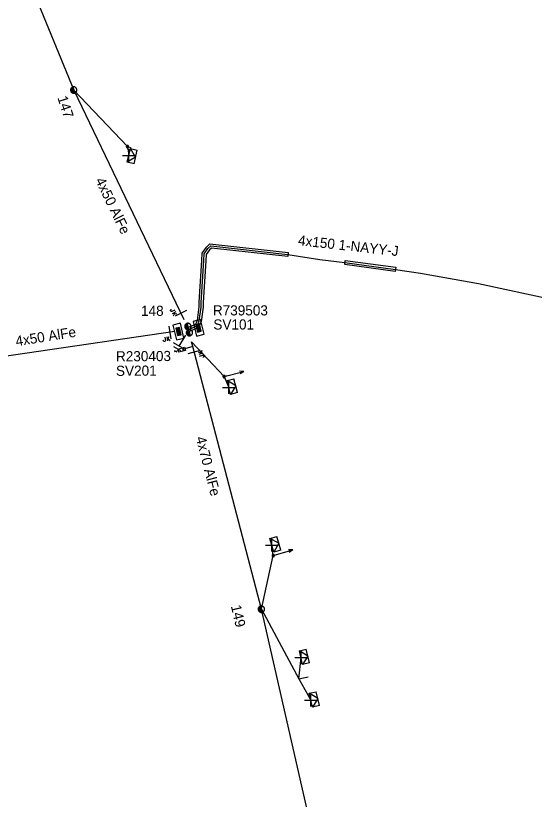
# Model space of a CAD drawing. Extents: x -544780 to -541582, y -1198995 to -1196551.
# Drawn here: x -542520.2 to -542469, y -1198913.7 to -1198836.4 of the extents above; entities that cross this region are included whole.
import ezdxf

# ---------------------------------------------------------------- set-up
doc = ezdxf.new("R2010")
doc.units = 0
for name, color, linetype in [('Vrstva 1', 7, 'Continuous'), ('Vrstva 13', 7, 'Continuous'), ('Vrstva 14', 7, 'Continuous'), ('Vrstva 15', 7, 'Continuous'), ('Vrstva 16', 7, 'Continuous'), ('Vrstva 18', 7, 'Continuous'), ('Vrstva 2', 7, 'Continuous'), ('Vrstva 20', 7, 'Continuous'), ('Vrstva 28', 7, 'Continuous'), ('Vrstva 29', 7, 'Continuous'), ('Vrstva 30', 7, 'Continuous'), ('Vrstva 31', 7, 'Continuous'), ('Vrstva 34', 7, 'Continuous'), ('Vrstva 5', 7, 'Continuous'), ('Vrstva 54', 7, 'Continuous'), ('Vrstva 59', 7, 'Continuous'), ('Vrstva 6', 7, 'Continuous'), ('Vrstva 8', 7, 'Continuous'), ('Vrstva 9', 7, 'Continuous')]:
    doc.layers.add(name, color=color, linetype=linetype)

# ---------------------------------------------------------------- blocks, each defined once
blk = doc.blocks.new('NN440')
at = {"layer": 'Vrstva 2'}
for points in [[(0.63, 0), (0.63, 0.06), (0.62, 0.13), (0.6, 0.19), (0.58, 0.25), (0.55, 0.31), (0.51, 0.37), (0.47, 0.42), (0.42, 0.46), (0.37, 0.51), (0.32, 0.54), (0.26, 0.57), (0.2, 0.59), (0.13, 0.61), (0.07, 0.62), (0, 0.63), (-0.06, 0.62), (-0.13, 0.61), (-0.19, 0.59), (-0.26, 0.57), (-0.31, 0.54), (-0.37, 0.51), (-0.42, 0.46), (-0.47, 0.42), (-0.51, 0.37), (-0.54, 0.31), (-0.57, 0.25), (-0.6, 0.19), (-0.62, 0.13), (-0.63, 0.06), (-0.63, 0), (-0.63, -0.07), (-0.62, -0.14), (-0.6, -0.2), (-0.57, -0.26), (-0.54, -0.32), (-0.51, -0.37), (-0.47, -0.43), (-0.42, -0.47), (-0.37, -0.51), (-0.31, -0.55), (-0.26, -0.58), (-0.19, -0.6), (-0.13, -0.62), (-0.06, -0.63), (0, -0.63), (0.07, -0.63), (0.13, -0.62), (0.2, -0.6), (0.26, -0.58), (0.32, -0.55), (0.37, -0.51), (0.42, -0.47), (0.47, -0.43), (0.51, -0.37), (0.55, -0.32), (0.58, -0.26), (0.6, -0.2), (0.62, -0.14), (0.63, -0.07), (0.63, 0)], [(-0.63, 0), (0.63, 0)], [(-0.6, -0.18), (0.57, -0.18)], [(-0.51, -0.32), (0.5, -0.32)], [(-0.37, -0.47), (0.35, -0.47)]]:
    blk.add_lwpolyline(points, dxfattribs=at)
blk = doc.blocks.new('NN450')
at = {"layer": 'Vrstva 2'}
for points in [[(0, 0), (0, 0.07), (-0.01, 0.13), (-0.03, 0.19), (-0.05, 0.25), (-0.08, 0.31), (-0.12, 0.37), (-0.16, 0.42), (-0.21, 0.46), (-0.26, 0.51), (-0.31, 0.54), (-0.37, 0.57), (-0.43, 0.59), (-0.5, 0.61), (-0.56, 0.62), (-0.63, 0.62), (-0.69, 0.62), (-0.75, 0.61), (-0.82, 0.59), (-0.88, 0.57), (-0.94, 0.54), (-0.99, 0.51), (-1.04, 0.46), (-1.09, 0.42), (-1.13, 0.37), (-1.17, 0.31), (-1.2, 0.25), (-1.22, 0.19), (-1.24, 0.13), (-1.25, 0.07), (-1.25, 0), (-1.25, -0.07), (-1.24, -0.13), (-1.22, -0.19), (-1.2, -0.25), (-1.17, -0.31), (-1.13, -0.37), (-1.09, -0.42), (-1.04, -0.46), (-0.99, -0.51), (-0.94, -0.54), (-0.88, -0.57), (-0.82, -0.59), (-0.75, -0.61), (-0.69, -0.62), (-0.62, -0.63), (-0.56, -0.62), (-0.5, -0.61), (-0.43, -0.59), (-0.37, -0.57), (-0.31, -0.54), (-0.26, -0.51), (-0.21, -0.46), (-0.16, -0.42), (-0.12, -0.37), (-0.08, -0.31), (-0.05, -0.25), (-0.03, -0.19), (-0.01, -0.13), (0, -0.07), (0, 0)], [(1.25, 0), (1.25, 0.07), (1.24, 0.13), (1.22, 0.19), (1.2, 0.25), (1.17, 0.31), (1.13, 0.37), (1.09, 0.42), (1.04, 0.46), (0.99, 0.51), (0.94, 0.54), (0.88, 0.57), (0.82, 0.59), (0.75, 0.61), (0.69, 0.62), (0.62, 0.62), (0.56, 0.62), (0.5, 0.61), (0.43, 0.59), (0.37, 0.57), (0.31, 0.54), (0.26, 0.51), (0.21, 0.46), (0.16, 0.42), (0.12, 0.37), (0.08, 0.31), (0.05, 0.25), (0.03, 0.19), (0.01, 0.13), (0, 0.07), (0, 0), (0, -0.07), (0.01, -0.13), (0.03, -0.19), (0.05, -0.25), (0.08, -0.31), (0.12, -0.37), (0.16, -0.42), (0.21, -0.46), (0.26, -0.51), (0.31, -0.54), (0.37, -0.57), (0.43, -0.59), (0.5, -0.61), (0.56, -0.62), (0.63, -0.63), (0.69, -0.62), (0.75, -0.61), (0.82, -0.59), (0.88, -0.57), (0.94, -0.54), (0.99, -0.51), (1.04, -0.46), (1.09, -0.42), (1.13, -0.37), (1.17, -0.31), (1.2, -0.25), (1.22, -0.19), (1.24, -0.13), (1.25, -0.07), (1.25, 0)], [(-1.25, 0), (1.25, 0)], [(-1.23, -0.16), (-0.02, -0.16)], [(-1.16, -0.32), (-0.09, -0.32)], [(-1.03, -0.47), (-0.22, -0.47)], [(0.02, -0.16), (1.23, -0.16)], [(0.09, -0.32), (1.16, -0.32)], [(0.22, -0.47), (1.03, -0.47)]]:
    blk.add_lwpolyline(points, dxfattribs=at)
blk = doc.blocks.new('NN560')
at = {"layer": 'Vrstva 2'}
for points in [[(1.999, -0.001), (1.59, 0.141)], [(0, -0.001), (1.999, -0.001)], [(1.999, -0.001), (1.59, -0.134)]]:
    blk.add_lwpolyline(points, dxfattribs=at)
blk = doc.blocks.new('NN840')
at = {"layer": 'Vrstva 15'}
for points in [[(0.003, 0.619), (0.003, -0.631)], [(-0.745, -0.71), (-0.745, -0.66)], [(-0.73, -0.764), (-0.745, -0.71)], [(-0.657, -0.798), (-0.73, -0.764)], [(-0.558, -0.764), (-0.627, -0.798)], [(-0.538, -0.71), (-0.558, -0.764)], [(-0.538, -0.385), (-0.538, -0.71)], [(-0.332, -0.385), (-0.332, -0.798)], [(-0.332, -0.641), (-0.125, -0.385)], [(-0.263, -0.557), (-0.091, -0.798)], [(-0.627, -0.798), (-0.657, -0.798)]]:
    blk.add_lwpolyline(points, dxfattribs=at)
blk = doc.blocks.new('NN800')
at = {"layer": 'Vrstva 1'}
for points in [[(-0.442, 0.442), (0.442, -0.442)], [(-0.442, -0.442), (0.442, 0.442)]]:
    blk.add_lwpolyline(points, dxfattribs=at)
blk = doc.blocks.new('NN820')
at = {"layer": 'Vrstva 13'}
for points in [[(-0.003, 0.004), (-0.003, -1.049)], [(-0.165, -0.813), (0.165, -0.813)], [(-0.165, -1.473), (-0.165, -0.813)], [(0.165, -1.473), (-0.165, -1.473)], [(-0.003, -1.049), (-0.062, -0.926)], [(-0.003, -1.049), (0.057, -0.926)], [(-0.003, -1.473), (-0.003, -1.871)], [(0.165, -0.813), (0.165, -1.473)]]:
    blk.add_lwpolyline(points, dxfattribs=at)
blk = doc.blocks.new('NN620')
at = {"layer": 'Vrstva 8'}
for points in [[(0.752, 0.004), (-0.748, 0.004)], [(-0.748, 0.004), (-0.748, -0.746)], [(0.752, -0.746), (0.752, 0.004)], [(-0.748, -0.746), (0.752, -0.746)], [(0.368, -0.18), (-0.376, -0.18)], [(-0.376, -0.18), (-0.376, -0.558)], [(-0.376, -0.558), (0.368, -0.558)], [(0.321, -0.227), (-0.329, -0.227)], [(-0.329, -0.227), (-0.329, -0.51)], [(-0.329, -0.51), (0.321, -0.51)], [(0.274, -0.274), (-0.281, -0.274)], [(-0.281, -0.274), (-0.281, -0.463)], [(-0.281, -0.463), (0.274, -0.463)], [(0.227, -0.321), (-0.234, -0.321)], [(-0.234, -0.321), (-0.234, -0.416)], [(-0.234, -0.416), (0.227, -0.416)], [(-0.193, -0.369), (0.185, -0.369)], [(0.227, -0.416), (0.227, -0.321)], [(0.274, -0.463), (0.274, -0.274)], [(0.321, -0.51), (0.321, -0.227)], [(0.368, -0.558), (0.368, -0.18)]]:
    blk.add_lwpolyline(points, dxfattribs=at)
blk = doc.blocks.new('NN630')
at = {"layer": 'Vrstva 9'}
for points in [[(-0.003, -0.7), (-0.703, 0)], [(-0.703, -0.7), (-0.703, 0), (0.697, 0), (0.697, -0.7)], [(-0.703, -0.7), (0.697, -0.7)], [(-0.003, -0.7), (0.697, 0)]]:
    blk.add_lwpolyline(points, dxfattribs=at)
blk = doc.blocks.new('NN810')
at = {"layer": 'Vrstva 14'}
for points in [[(0.004, -0.64), (0.004, -1.89)], [(0.629, -1.89), (-0.621, -1.89)], [(0.388, -2.2), (-0.399, -2.2)], [(0.004, -2.515), (-0.124, -2.515)], [(0.137, -2.515), (0.004, -2.515)]]:
    blk.add_lwpolyline(points, dxfattribs=at)
blk = doc.blocks.new('NN500')
at = {"layer": 'Vrstva 2'}
for points in [[(0, -0.24), (0.02, -0.23), (0.05, -0.23), (0.07, -0.22), (0.09, -0.22), (0.12, -0.2), (0.14, -0.19), (0.16, -0.18), (0.17, -0.16), (0.19, -0.14), (0.2, -0.12), (0.21, -0.1), (0.22, -0.07), (0.23, -0.05), (0.23, -0.02), (0.23, 0), (0.23, 0.02), (0.23, 0.05), (0.22, 0.07), (0.21, 0.1), (0.2, 0.12), (0.19, 0.14), (0.17, 0.16), (0.16, 0.17), (0.14, 0.19), (0.12, 0.2), (0.09, 0.21), (0.07, 0.22), (0.05, 0.23), (0.02, 0.23), (0, 0.23), (-0.03, 0.23), (-0.05, 0.23), (-0.07, 0.22), (-0.1, 0.21), (-0.12, 0.2), (-0.14, 0.19), (-0.16, 0.17), (-0.18, 0.16), (-0.19, 0.14), (-0.2, 0.12), (-0.22, 0.1), (-0.22, 0.07), (-0.23, 0.05), (-0.23, 0.02), (-0.24, 0), (-0.23, -0.02), (-0.23, -0.05), (-0.22, -0.07), (-0.22, -0.1), (-0.2, -0.12), (-0.19, -0.14), (-0.18, -0.16), (-0.16, -0.18), (-0.14, -0.19), (-0.12, -0.2), (-0.1, -0.22), (-0.07, -0.22), (-0.05, -0.23), (-0.03, -0.23), (0, -0.24)], [(0, -0.24), (0.02, -0.23), (0.05, -0.23), (0.07, -0.22), (0.09, -0.22), (0.12, -0.2), (0.14, -0.19), (0.16, -0.18), (0.17, -0.16), (0.19, -0.14), (0.2, -0.12), (0.21, -0.1), (0.22, -0.07), (0.23, -0.05), (0.23, -0.02), (0.23, 0), (0.23, 0.02), (0.23, 0.05), (0.22, 0.07), (0.21, 0.1), (0.2, 0.12), (0.19, 0.14), (0.17, 0.16), (0.16, 0.17), (0.14, 0.19), (0.12, 0.2), (0.09, 0.21), (0.07, 0.22), (0.05, 0.23), (0.02, 0.23), (0, 0.23), (-0.03, 0.23), (-0.05, 0.23), (-0.07, 0.22), (-0.1, 0.21), (-0.12, 0.2), (-0.14, 0.19), (-0.16, 0.17), (-0.18, 0.16), (-0.19, 0.14), (-0.2, 0.12), (-0.22, 0.1), (-0.22, 0.07), (-0.23, 0.05), (-0.23, 0.02), (-0.24, 0), (-0.23, -0.02), (-0.23, -0.05), (-0.22, -0.07), (-0.22, -0.1), (-0.2, -0.12), (-0.19, -0.14), (-0.18, -0.16), (-0.16, -0.18), (-0.14, -0.19), (-0.12, -0.2), (-0.1, -0.22), (-0.07, -0.22), (-0.05, -0.23), (-0.03, -0.23), (0, -0.24)], [(0, -0.21), (0.02, -0.2), (0.04, -0.2), (0.06, -0.2), (0.08, -0.19), (0.1, -0.18), (0.12, -0.17), (0.14, -0.15), (0.15, -0.14), (0.16, -0.12), (0.18, -0.1), (0.19, -0.08), (0.19, -0.06), (0.2, -0.04), (0.2, -0.02), (0.2, 0), (0.2, 0.02), (0.2, 0.04), (0.19, 0.06), (0.19, 0.08), (0.18, 0.1), (0.16, 0.12), (0.15, 0.14), (0.14, 0.15), (0.12, 0.17), (0.1, 0.18), (0.08, 0.19), (0.06, 0.19), (0.04, 0.2), (0.02, 0.2), (0, 0.2), (-0.02, 0.2), (-0.04, 0.2), (-0.06, 0.19), (-0.08, 0.19), (-0.1, 0.18), (-0.12, 0.17), (-0.14, 0.15), (-0.15, 0.14), (-0.17, 0.12), (-0.18, 0.1), (-0.19, 0.08), (-0.2, 0.06), (-0.2, 0.04), (-0.21, 0.02), (-0.21, 0), (-0.21, -0.02), (-0.2, -0.04), (-0.2, -0.06), (-0.19, -0.08), (-0.18, -0.1), (-0.17, -0.12), (-0.15, -0.14), (-0.14, -0.15), (-0.12, -0.17), (-0.1, -0.18), (-0.08, -0.19), (-0.06, -0.2), (-0.04, -0.2), (-0.02, -0.2), (0, -0.21)], [(0, -0.18), (0.02, -0.18), (0.04, -0.17), (0.05, -0.17), (0.07, -0.16), (0.09, -0.15), (0.1, -0.14), (0.12, -0.13), (0.13, -0.12), (0.14, -0.1), (0.15, -0.09), (0.16, -0.07), (0.17, -0.05), (0.17, -0.04), (0.17, -0.02), (0.17, 0), (0.17, 0.02), (0.17, 0.04), (0.17, 0.05), (0.16, 0.07), (0.15, 0.09), (0.14, 0.1), (0.13, 0.12), (0.12, 0.13), (0.1, 0.14), (0.09, 0.15), (0.07, 0.16), (0.05, 0.17), (0.04, 0.17), (0.02, 0.17), (0, 0.18), (-0.02, 0.17), (-0.04, 0.17), (-0.06, 0.17), (-0.07, 0.16), (-0.09, 0.15), (-0.1, 0.14), (-0.12, 0.13), (-0.13, 0.12), (-0.14, 0.1), (-0.15, 0.09), (-0.16, 0.07), (-0.17, 0.05), (-0.17, 0.04), (-0.18, 0.02), (-0.18, 0), (-0.18, -0.02), (-0.17, -0.04), (-0.17, -0.05), (-0.16, -0.07), (-0.15, -0.09), (-0.14, -0.1), (-0.13, -0.12), (-0.12, -0.13), (-0.1, -0.14), (-0.09, -0.15), (-0.07, -0.16), (-0.06, -0.17), (-0.04, -0.17), (-0.02, -0.18), (0, -0.18)], [(0, -0.15), (0.01, -0.15), (0.03, -0.14), (0.04, -0.14), (0.06, -0.13), (0.07, -0.13), (0.08, -0.12), (0.1, -0.11), (0.11, -0.1), (0.12, -0.09), (0.13, -0.07), (0.13, -0.06), (0.14, -0.05), (0.14, -0.03), (0.14, -0.02), (0.14, 0), (0.14, 0.01), (0.14, 0.03), (0.14, 0.04), (0.13, 0.06), (0.13, 0.07), (0.12, 0.09), (0.11, 0.1), (0.1, 0.11), (0.08, 0.12), (0.07, 0.13), (0.06, 0.13), (0.04, 0.14), (0.03, 0.14), (0.01, 0.14), (0, 0.15), (-0.02, 0.14), (-0.03, 0.14), (-0.05, 0.14), (-0.06, 0.13), (-0.07, 0.13), (-0.09, 0.12), (-0.1, 0.11), (-0.11, 0.1), (-0.12, 0.09), (-0.13, 0.07), (-0.13, 0.06), (-0.14, 0.04), (-0.14, 0.03), (-0.15, 0.01), (-0.15, 0), (-0.15, -0.02), (-0.14, -0.03), (-0.14, -0.05), (-0.13, -0.06), (-0.13, -0.07), (-0.12, -0.09), (-0.11, -0.1), (-0.1, -0.11), (-0.09, -0.12), (-0.07, -0.13), (-0.06, -0.13), (-0.05, -0.14), (-0.03, -0.14), (-0.02, -0.15), (0, -0.15)], [(0, -0.12), (0.01, -0.12), (0.02, -0.11), (0.03, -0.11), (0.05, -0.11), (0.06, -0.1), (0.07, -0.09), (0.08, -0.09), (0.09, -0.08), (0.09, -0.07), (0.1, -0.06), (0.11, -0.05), (0.11, -0.04), (0.11, -0.02), (0.11, -0.01), (0.12, 0), (0.11, 0.01), (0.11, 0.02), (0.11, 0.04), (0.11, 0.05), (0.1, 0.06), (0.09, 0.07), (0.09, 0.08), (0.08, 0.09), (0.07, 0.09), (0.06, 0.1), (0.05, 0.11), (0.03, 0.11), (0.02, 0.11), (0.01, 0.12), (0, 0.12), (-0.01, 0.12), (-0.03, 0.11), (-0.04, 0.11), (-0.05, 0.11), (-0.06, 0.1), (-0.07, 0.09), (-0.08, 0.09), (-0.09, 0.08), (-0.1, 0.07), (-0.1, 0.06), (-0.11, 0.05), (-0.11, 0.04), (-0.12, 0.02), (-0.12, 0.01), (-0.12, 0), (-0.12, -0.01), (-0.12, -0.02), (-0.11, -0.04), (-0.11, -0.05), (-0.1, -0.06), (-0.1, -0.07), (-0.09, -0.08), (-0.08, -0.09), (-0.07, -0.09), (-0.06, -0.1), (-0.05, -0.11), (-0.04, -0.11), (-0.03, -0.11), (-0.01, -0.12), (0, -0.12)], [(0, -0.09), (0.01, -0.09), (0.02, -0.09), (0.03, -0.08), (0.03, -0.08), (0.04, -0.08), (0.05, -0.07), (0.06, -0.07), (0.06, -0.06), (0.07, -0.05), (0.07, -0.04), (0.08, -0.04), (0.08, -0.03), (0.08, -0.02), (0.09, -0.01), (0.09, 0), (0.09, 0.01), (0.08, 0.02), (0.08, 0.03), (0.08, 0.03), (0.07, 0.04), (0.07, 0.05), (0.06, 0.06), (0.06, 0.06), (0.05, 0.07), (0.04, 0.07), (0.03, 0.08), (0.03, 0.08), (0.02, 0.08), (0.01, 0.09), (0, 0.09), (-0.01, 0.09), (-0.02, 0.08), (-0.03, 0.08), (-0.04, 0.08), (-0.04, 0.07), (-0.05, 0.07), (-0.06, 0.06), (-0.07, 0.06), (-0.07, 0.05), (-0.08, 0.04), (-0.08, 0.03), (-0.08, 0.03), (-0.09, 0.02), (-0.09, 0.01), (-0.09, 0), (-0.09, -0.01), (-0.09, -0.02), (-0.08, -0.03), (-0.08, -0.04), (-0.08, -0.04), (-0.07, -0.05), (-0.07, -0.06), (-0.06, -0.07), (-0.05, -0.07), (-0.04, -0.08), (-0.04, -0.08), (-0.03, -0.08), (-0.02, -0.09), (-0.01, -0.09), (0, -0.09)], [(0, -0.06), (0, -0.06), (0.01, -0.06), (0.02, -0.05), (0.02, -0.05), (0.03, -0.05), (0.03, -0.05), (0.04, -0.04), (0.04, -0.04), (0.05, -0.03), (0.05, -0.03), (0.05, -0.02), (0.05, -0.02), (0.05, -0.01), (0.06, -0.01), (0.06, 0), (0.06, 0.01), (0.05, 0.01), (0.05, 0.02), (0.05, 0.02), (0.05, 0.03), (0.05, 0.03), (0.04, 0.04), (0.04, 0.04), (0.03, 0.05), (0.03, 0.05), (0.02, 0.05), (0.02, 0.05), (0.01, 0.06), (0, 0.06), (0, 0.06), (-0.01, 0.06), (-0.01, 0.06), (-0.02, 0.05), (-0.02, 0.05), (-0.03, 0.05), (-0.03, 0.05), (-0.04, 0.04), (-0.04, 0.04), (-0.05, 0.03), (-0.05, 0.03), (-0.05, 0.02), (-0.06, 0.02), (-0.06, 0.01), (-0.06, 0.01), (-0.06, 0), (-0.06, -0.01), (-0.06, -0.01), (-0.06, -0.02), (-0.05, -0.02), (-0.05, -0.03), (-0.05, -0.03), (-0.04, -0.04), (-0.04, -0.04), (-0.03, -0.05), (-0.03, -0.05), (-0.02, -0.05), (-0.02, -0.05), (-0.01, -0.06), (-0.01, -0.06), (0, -0.06)], [(0, -0.03), (0, -0.03), (0, -0.03), (0.01, -0.03), (0.01, -0.03), (0.01, -0.02), (0.02, -0.02), (0.02, -0.02), (0.02, -0.02), (0.02, -0.02), (0.02, -0.01), (0.02, -0.01), (0.03, -0.01), (0.03, -0.01), (0.03, 0), (0.03, 0), (0.03, 0), (0.03, 0.01), (0.03, 0.01), (0.02, 0.01), (0.02, 0.01), (0.02, 0.02), (0.02, 0.02), (0.02, 0.02), (0.02, 0.02), (0.01, 0.02), (0.01, 0.02), (0.01, 0.03), (0, 0.03), (0, 0.03), (0, 0.03), (0, 0.03), (-0.01, 0.03), (-0.01, 0.03), (-0.01, 0.02), (-0.02, 0.02), (-0.02, 0.02), (-0.02, 0.02), (-0.02, 0.02), (-0.02, 0.02), (-0.03, 0.01), (-0.03, 0.01), (-0.03, 0.01), (-0.03, 0.01), (-0.03, 0), (-0.03, 0), (-0.03, 0), (-0.03, -0.01), (-0.03, -0.01), (-0.03, -0.01), (-0.03, -0.01), (-0.02, -0.02), (-0.02, -0.02), (-0.02, -0.02), (-0.02, -0.02), (-0.02, -0.02), (-0.01, -0.03), (-0.01, -0.03), (-0.01, -0.03), (0, -0.03), (0, -0.03)], [(0.23, 0), (0.7, 0)]]:
    blk.add_lwpolyline(points, dxfattribs=at)
blk = doc.blocks.new('NN510')
at = {"layer": 'Vrstva 2'}
blk.add_lwpolyline([(0.001, 0.002), (0.001, 0.939)], dxfattribs=at)

msp = doc.modelspace()

# ---------------------------------------------------------------- linework, layer by layer
at = {"layer": 'Vrstva 1'}
for points in [[(-542577.967, -1198687.899), (-542564.274, -1198718.66), (-542554.42, -1198740.423), (-542545.379, -1198761.199), (-542536.43, -1198781.957), (-542527.209, -1198812.773), (-542514.462, -1198843.761), (-542503.597, -1198866.404)], [(-542504.472, -1198867.595), (-542526.501, -1198870.797)], [(-542475.347, -1198994.15), (-542476.818, -1198975.71), (-542483.119, -1198949.335), (-542488.815, -1198926.134), (-542495.947, -1198894.974), (-542502.711, -1198869.077), (-542502.843, -1198868.609)]]:
    msp.add_lwpolyline(points, dxfattribs=at)
at = {"layer": 'Vrstva 20'}
for points in [[(-542493.352, -1198860.179), (-542500.881, -1198859.349), (-542501.067, -1198859.521), (-542501.384, -1198859.987), (-542501.42, -1198860.602), (-542501.68, -1198864.716), (-542501.68, -1198865.184), (-542501.875, -1198866.582), (-542502.105, -1198867.149), (-542503.029, -1198867.568), (-542503.194, -1198867.204), (-542502.415, -1198866.851), (-542502.265, -1198866.478), (-542502.08, -1198865.156), (-542502.08, -1198864.704), (-542501.82, -1198860.578), (-542501.776, -1198859.853), (-542501.373, -1198859.259), (-542501.019, -1198858.931), (-542493.308, -1198859.781)], [(-542487.673, -1198860.572), (-542482.683, -1198861.252), (-542482.737, -1198861.648), (-542487.727, -1198860.968)]]:
    msp.add_lwpolyline(points, close=True, dxfattribs=at)
at = {"layer": 'Vrstva 5'}
msp.add_lwpolyline([(-542503.12, -1198867.39), (-542502.26, -1198867), (-542502.07, -1198866.53), (-542501.88, -1198865.17), (-542501.88, -1198864.71), (-542501.62, -1198860.59), (-542501.58, -1198859.92), (-542501.22, -1198859.39), (-542500.95, -1198859.14), (-542493.33, -1198859.98), (-542490.19, -1198860.48), (-542487.7, -1198860.77), (-542482.71, -1198861.45), (-542480.24, -1198861.83), (-542474.51, -1198862.84), (-542467.19, -1198864.42)], dxfattribs=at)
at = {"layer": 'Vrstva 54'}
for points in [[(-542514.462, -1198843.761), (-542509.158, -1198849.338), (-542509.034, -1198850.21)], [(-542502.843, -1198868.609), (-542499.621, -1198872.021), (-542499.157, -1198873.104)], [(-542495.947, -1198894.974), (-542494.773, -1198889.684), (-542494.91, -1198888.66)], [(-542495.947, -1198894.974), (-542492.241, -1198901.845)]]:
    msp.add_lwpolyline(points, dxfattribs=at)
at = {"layer": 'Vrstva 59'}
for points in [[(-542492.241, -1198901.845), (-542492.037, -1198899.75)], [(-542492.241, -1198901.845), (-542491.063, -1198903.953)]]:
    msp.add_lwpolyline(points, dxfattribs=at)

# ---------------------------------------------------------------- block references
at = {"layer": 'Vrstva 13'}
for name, p, xscale, yscale, rotation in [('NN440', (-542514.462, -1198843.761), 0.5, 0.5, -72.06666669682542), ('NN500', (-542509.158, -1198849.338), 0.49999999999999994, 0.5000000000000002, -13.110999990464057), ('NN450', (-542503.12, -1198867.39), 0.49999999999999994, 0.5000000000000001, -76.15550290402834), ('NN500', (-542499.621, -1198872.021), 0.5, 0.5, 14.792999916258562), ('NN500', (-542494.773, -1198889.684), 0.5, 0.5, 16.011000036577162), ('NN440', (-542495.947, -1198894.973), 0.5, 0.5, -76.94833332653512)]:
    msp.add_blockref(name, p, dxfattribs=dict(at, xscale=xscale, yscale=yscale, rotation=rotation))
for name, p, rotation in [('NN560', (-542499.621, -1198872.021), 14.793202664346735), ('NN560', (-542494.773, -1198889.684), 16.01078061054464), ('NN510', (-542492.242, -1198901.845), -76.94833336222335)]:
    msp.add_blockref(name, p, dxfattribs=dict(at, rotation=rotation))
at = {"layer": 'Vrstva 15', "rotation": -30.544143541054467}
msp.add_blockref('NN810', (-542503.12, -1198867.39), dxfattribs=at)
at = {"layer": 'Vrstva 16', "rotation": -74.20354883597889}
msp.add_blockref('NN820', (-542502.711, -1198869.077), dxfattribs=at)
at = {"layer": 'Vrstva 18'}
for p, rotation in [((-542503.894, -1198865.787), -64.0942110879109), ((-542504.994, -1198867.678), 9.15404449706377), ((-542502.562, -1198869.601), 105.81641403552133)]:
    msp.add_blockref('NN840', p, dxfattribs=dict(at, rotation=rotation))
at = {"layer": 'Vrstva 28'}
for p, rotation in [((-542502.508, -1198867.31), 103.84449709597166), ((-542503.771, -1198867.498), -76.70919858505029)]:
    msp.add_blockref('NN620', p, dxfattribs=dict(at, rotation=rotation))
at = {"layer": 'Vrstva 31'}
for p, rotation in [((-542509.034, -1198850.21), 76.88864171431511), ((-542499.157, -1198873.104), 104.79320277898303), ((-542494.91, -1198888.66), 106.01078049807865), ((-542492.037, -1198899.75), 103.05166663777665), ((-542491.063, -1198903.953), 103.05166663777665)]:
    msp.add_blockref('NN630', p, dxfattribs=dict(at, rotation=rotation))
at = {"layer": 'Vrstva 34', "rotation": 45}
for p in [(-542509.034, -1198850.21), (-542499.157, -1198873.104), (-542494.91, -1198888.66), (-542492.037, -1198899.75), (-542491.063, -1198903.953)]:
    msp.add_blockref('NN800', p, dxfattribs=at)

# ---------------------------------------------------------------- texts
at = {"layer": 'Vrstva 14'}
for s, rotation, p in [('147', 287.933, (-542516.082, -1198844.516)), ('148', 0.006, (-542507.819, -1198866.038)), ('149', 283.052, (-542498.962, -1198894.665))]:
    msp.add_text(s, height=1, rotation=rotation, dxfattribs=at).set_placement(p)
at = {"layer": 'Vrstva 2'}
for s, rotation, p in [('4x50 AlFe', 295.837, (-542512.36, -1198852.675)), ('4x50 AlFe', 9.155, (-542520.121, -1198869.045)), ('4x70 AlFe', 284.439, (-542502.428, -1198878.069))]:
    msp.add_text(s, height=1, rotation=rotation, dxfattribs=at).set_placement(p)
at = {"layer": 'Vrstva 29'}
msp.add_text('R739503', height=1, dxfattribs=at).set_placement((-542500.732, -1198865.997))
msp.add_text('R230403', height=1, rotation=0.387, dxfattribs=at).set_placement((-542510.29, -1198870.532))
at = {"layer": 'Vrstva 30'}
msp.add_text('SV101', height=1, dxfattribs=at).set_placement((-542500.685, -1198867.388))
msp.add_text('SV201', height=1, rotation=0.387, dxfattribs=at).set_placement((-542510.288, -1198871.962))
at = {"layer": 'Vrstva 6'}
msp.add_text('4x150 1-NAYY-J', height=1, rotation=353.709, dxfattribs=at).set_placement((-542492.368, -1198859.064))

doc.saveas('drawing.dxf')
